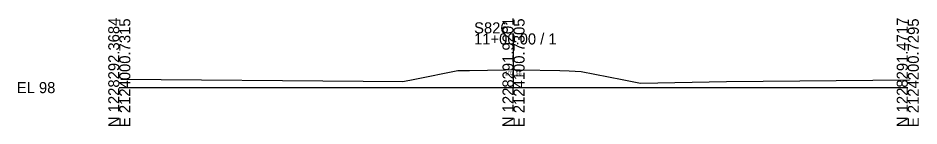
# Model space of a CAD drawing. Extents: x 2118382 to 2118616, y 1213030 to 1222057.
# Drawn here: x 2118381.9 to 2118610.4, y 1221530.1 to 1221557.4 of the extents above; entities that cross this region are included whole.
import ezdxf

# ---------------------------------------------------------------- set-up
doc = ezdxf.new("R2010")
doc.units = 0
for name, color, linetype in [('XS_CELL', 7, 'Continuous'), ('XS_X_GROUND', 7, 'Continuous'), ('XS_X_GROUND_TX', 7, 'Continuous')]:
    doc.layers.add(name, color=color, linetype=linetype)

msp = doc.modelspace()

# ---------------------------------------------------------------- linework, layer by layer
at = {"layer": 'XS_CELL'}
for p, q in [((2118507.6, 1221539.8), (2118507.6, 1221553.51)), ((2118407.6, 1221539.8), (2118507.6, 1221539.8)), ((2118507.6, 1221539.8), (2118607.6, 1221539.8))]:
    msp.add_line(p, q, dxfattribs=at)
at = {"layer": 'XS_X_GROUND'}
for p, q in [((2118482.56, 1221541.91), (2118493.43, 1221544.14)), ((2118493.43, 1221544.14), (2118494.69, 1221544.13)), ((2118494.69, 1221544.13), (2118496.4, 1221544.15)), ((2118496.4, 1221544.15), (2118505.53, 1221544.33)), ((2118505.53, 1221544.33), (2118507.6, 1221544.36)), ((2118507.6, 1221544.36), (2118508.02, 1221544.36)), ((2118508.02, 1221544.36), (2118509.25, 1221544.33)), ((2118509.25, 1221544.33), (2118519.31, 1221544.16)), ((2118519.31, 1221544.16), (2118521.68, 1221544.04)), ((2118521.68, 1221544.04), (2118524.78, 1221543.86)), ((2118524.78, 1221543.86), (2118535.15, 1221541.83)), ((2118408.02, 1221541.96), (2118469.44, 1221541.42)), ((2118469.44, 1221541.42), (2118479.52, 1221541.32)), ((2118479.52, 1221541.32), (2118482.56, 1221541.91)), ((2118535.15, 1221541.83), (2118539.78, 1221540.96)), ((2118539.78, 1221540.96), (2118561.59, 1221541.34)), ((2118561.59, 1221541.34), (2118608.02, 1221541.74))]:
    msp.add_line(p, q, dxfattribs=at)

# ---------------------------------------------------------------- texts
at = {"layer": 'XS_CELL'}
for s, p in [('N 1228292.3684', (2118407.6, 1221529.8)), ('E 2124000.7315', (2118410.4, 1221529.8)), ('N 1228291.9201', (2118507.6, 1221529.8)), ('E 2124100.7305', (2118510.4, 1221529.8)), ('N 1228291.4717', (2118607.6, 1221529.8)), ('E 2124200.7295', (2118610.4, 1221529.8))]:
    msp.add_text(s, height=2.8, rotation=90, dxfattribs=at).set_placement(p)
for s, p in [('S826', (2118497.6, 1221553.51)), ('11+00.00 / 1', (2118497.6, 1221550.71)), ('EL 98', (2118381.6, 1221538.4))]:
    msp.add_text(s, height=2.8, dxfattribs=at).set_placement(p)
at = {"layer": 'XS_X_GROUND_TX'}
msp.add_text('102.56', height=1, dxfattribs=at).set_placement((2118505.42, 1221542.93))

doc.saveas('drawing.dxf')
